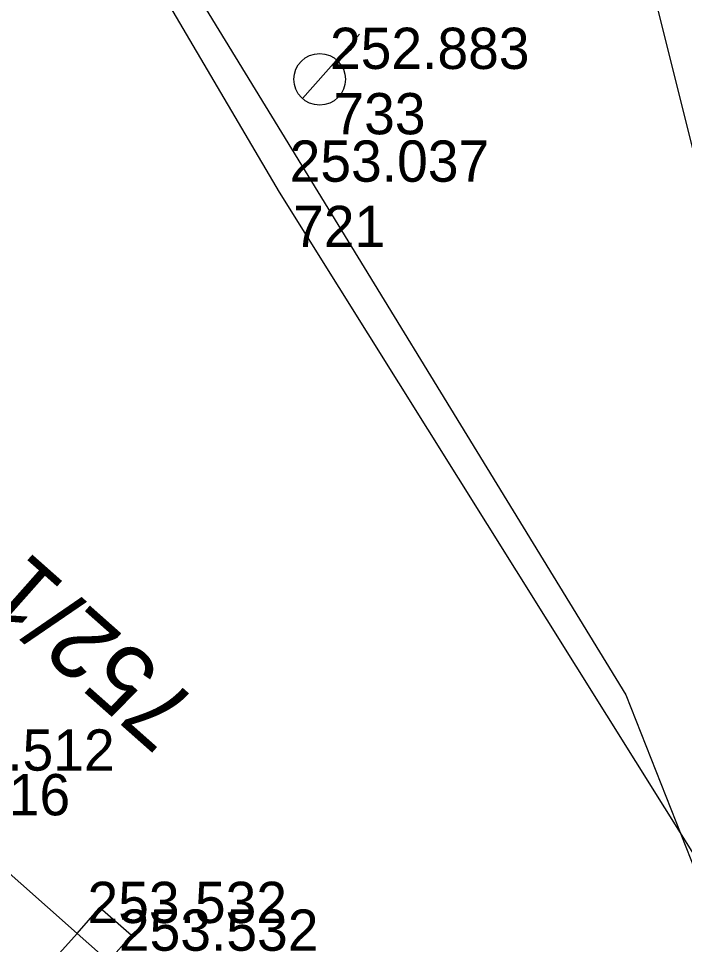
# Model space of a CAD drawing. Extents: x -496688 to -495455, y -1089309 to -1088026.
# Drawn here: x -495948.81 to -495929.45, y -1088634.51 to -1088607.59 of the extents above; entities that cross this region are included whole.
import ezdxf

# ---------------------------------------------------------------- set-up
doc = ezdxf.new("R2010")
doc.units = 0
for name, color, linetype in [('Vrstva 1', 7, 'Continuous'), ('Vrstva 4', 7, 'Continuous'), ('Vrstva 47', 7, 'Continuous'), ('Vrstva 53', 7, 'Continuous'), ('Vrstva 56', 7, 'Continuous'), ('Vrstva 57', 7, 'Continuous'), ('Vrstva 60', 7, 'Continuous'), ('Vrstva 61', 7, 'Continuous')]:
    doc.layers.add(name, color=color, linetype=linetype)

msp = doc.modelspace()

# ---------------------------------------------------------------- linework, layer by layer
at = {"layer": 'Vrstva 1'}
for points in [[(-495794.281, -1088769.662), (-495806.718, -1088758.644), (-495819.114, -1088747.662), (-495828.107, -1088739.648), (-495840.608, -1088728.579), (-495852.984, -1088717.621), (-495860.029, -1088711.42), (-495872.461, -1088700.397), (-495884.955, -1088689.319), (-495893.533, -1088681.721), (-495913.179, -1088664.263), (-495947.105, -1088634.191), (-495952.116, -1088629.76), (-495964.613, -1088618.686), (-495984.901, -1088600.717), (-495997.336, -1088589.715), (-496002.819, -1088584.884), (-496021.751, -1088568.167), (-496024.418, -1088565.811), (-496062.504, -1088532.205), (-496086.773, -1088510.767), (-496106.199, -1088493.629), (-496127.249, -1088474.987), (-496164.633, -1088441.927)], [(-495941.228, -1088612.636), (-495960.706, -1088579.532), (-495969.885, -1088563.939), (-495982.474, -1088542.537), (-495998.352, -1088515.291)], [(-495883.707, -1088687.975), (-495885.058, -1088686.472), (-495891.052, -1088679.853), (-495901.24, -1088668.642), (-495909.888, -1088658.649), (-495924.816, -1088638.862), (-495941.228, -1088612.636)]]:
    msp.add_lwpolyline(points, dxfattribs=at)
at = {"layer": 'Vrstva 4'}
msp.add_lwpolyline([(-495955.503, -1088645.516), (-495956.17, -1088646.261), (-495957.074, -1088645.452), (-495956.407, -1088644.707), (-495954.862, -1088642.985), (-495953.413, -1088641.405), (-495950.229, -1088637.776), (-495948.839, -1088636.121), (-495947.105, -1088634.191), (-495946.443, -1088633.441), (-495945.53, -1088634.247), (-495946.192, -1088634.997), (-495948.022, -1088637.028), (-495949.318, -1088638.59), (-495952.505, -1088642.214), (-495953.864, -1088643.689), (-495955.503, -1088645.516)], dxfattribs=at)
at = {"layer": 'Vrstva 47'}
msp.add_line((-495940.554, -1088609.918), (-495938.895, -1088608.047), dxfattribs=at)
msp.add_circle((-495940.056, -1088609.357), 0.75, dxfattribs=at)
at = {"layer": 'Vrstva 53'}
msp.add_lwpolyline([(-496003.534, -1088369.744), (-496002.28, -1088375.11), (-496002.19, -1088375.66), (-496000.91, -1088380.74), (-496000.83, -1088381.05), (-495997.31, -1088380.16), (-495982.62, -1088436.04), (-495950.27, -1088527.28), (-495948.71, -1088533.28), (-495927, -1088620.27), (-495919.06, -1088642.9), (-495909.37, -1088663.33), (-495876.99, -1088692.49)], dxfattribs=at)
at = {"layer": 'Vrstva 56'}
for p, q in [((-495954.14, -1088589.68), (-495931.16, -1088627.26)), ((-495931.16, -1088627.26), (-495921.08, -1088652.79))]:
    msp.add_line(p, q, dxfattribs=at)
at = {"layer": 'Vrstva 60'}
for p, q in [((-495940.056, -1088609.357), (-495940.056, -1088609.357)), ((-495940.056, -1088609.357), (-495940.056, -1088609.357)), ((-495941.228, -1088612.636), (-495941.228, -1088612.636)), ((-495941.228, -1088612.636), (-495941.228, -1088612.636)), ((-495947.105, -1088634.191), (-495947.105, -1088634.191)), ((-495947.105, -1088634.191), (-495947.105, -1088634.191))]:
    msp.add_line(p, q, dxfattribs=at)

# ---------------------------------------------------------------- texts
at = {"layer": 'Vrstva 57'}
msp.add_text('752/1', height=2, rotation=138.4565, dxfattribs=at).set_placement((-495943.497, -1088627.53))
at = {"layer": 'Vrstva 60'}
for s, p in [('733', (-495939.656, -1088610.957)), ('733', (-495939.656, -1088610.957)), ('721', (-495940.828, -1088614.236)), ('721', (-495940.828, -1088614.236))]:
    msp.add_text(s, height=1.2, dxfattribs=at).set_placement(p)
at = {"layer": 'Vrstva 61'}
for s, p in [('252.883', (-495939.756, -1088609.057)), ('252.883', (-495939.756, -1088609.057)), ('253.037', (-495940.928, -1088612.336)), ('253.037', (-495940.928, -1088612.336)), ('253.512', (-495951.816, -1088629.46)), ('253.512', (-495951.816, -1088629.46)), ('253.516', (-495953.109, -1088630.759)), ('253.516', (-495953.109, -1088630.759)), ('253.532', (-495946.805, -1088633.891)), ('253.532', (-495946.805, -1088633.891)), ('253.532', (-495945.892, -1088634.697)), ('253.532', (-495945.892, -1088634.697))]:
    msp.add_text(s, height=1.2, dxfattribs=at).set_placement(p)

doc.saveas('drawing.dxf')
